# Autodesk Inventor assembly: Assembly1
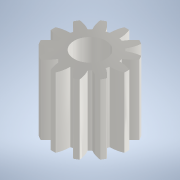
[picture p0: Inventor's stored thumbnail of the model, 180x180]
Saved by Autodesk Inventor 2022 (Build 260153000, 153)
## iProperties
Created: 2024-12
Part Number: Assembly1
Document SubType Name: Assembly
Designer: jsat7
Author: jsat7
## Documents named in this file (2)
- C:\Users\jsat7\OneDrive\デスクトップ\CAD 長田\Assembly1.iam
- C:\Users\jsat7\OneDrive\デスクトップ\CAD 長田\Assembly1\デザイン アクセラレータ\平歯車1.iam
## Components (1 placed, 1 different names)
1. 平歯車:1 [sub-assembly]
